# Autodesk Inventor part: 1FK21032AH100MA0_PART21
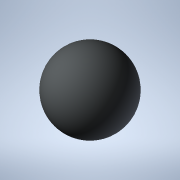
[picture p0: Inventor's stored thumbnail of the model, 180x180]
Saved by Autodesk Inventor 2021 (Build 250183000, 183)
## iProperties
Created: 2025-04
Part Number: 1FK21032AH100MA0_PART21
Material: Generic
Catalog Web Link: www.3dfindit.com
Description: -Servo synchronous motor
Document SubType Name: Modeling
Designer: psAdmin
Mass: 0.113097 g
Surface Area: 1.13097 cm^2
Volume: 0.113097 cm^3
Density: 1 g/cm^3
Appearance: PSOLRGB-212-217-219
Category: PARTsolutions
Title: 1FK21032AH100MA0_PART21
Author: Cadenas PARTsolutions
Comments: Servo synchronous motor
Sending System: PARTsolutions
Preprocessor: ST-DEVELOPER v19.3
PSOL_IDENT_0: {$CADENAS_DATA/23d-libs/siemens_ag/_cat_/12/33/1fk21032ah100ma0.prj},216 {VTYP=3D},{NB=1FK21032AH100
PSOL_IDENT_1: MA0_PART21},{LINA=1FK21032AH100MA0_PART21},{NN=1FK21032AH100MA0_PART21},{NOPRJ=TRUE},{DATE=19.08.202
PSOL_IDENT_2: 5 14:00:27},{GEOMDATE=30.07.2025 02:02:58},{VERSION=},{LINEID=10},{WBVAR=},{WBNUMERIC=}  {NB=1FK2103
PSOL_IDENT_3: 2AH100MA0_PART21},{LINA=1FK21032AH100MA0_PART21},{KT=DUMMY},{PREVIEW=../../../_pool_/d3/78/p_d211_xx
PSOL_IDENT_4: _00934j.png},{DESCSHORT=SIMOTICS S-1FK2 HD, SINAMICS S210 3AC 400V-480V, 0.59 Nm, 4500 rpm},{DESCLON
PSOL_IDENT_5: G=SIMOTICS S-1FK2 HD servo motor M0=0.64 Nm; PN = 0.28 kW at nN=4500 rpm (380-480 V); PN = 0.167 kW
PSOL_IDENT_6: at nN=2500 rpm (200-240 V); with holding brake; degree of protection IP64; cylindrical shaft D14 x 3
PSOL_IDENT_7: 0 mm; absolute encoder 22-bit + 12-bit multiturn (encoder AM22DQC); with OCC interface; plug size M1
PSOL_IDENT_8: 7, rotatable; SIMOTICS S-1FK2 servomotorfor a wide range of uses in industrial environments. SIMOTIC
PSOL_IDENT_9: S S‑1FK2 servomotors are compact synchronous motors with a high dynamic performance that set themsel
PSOL_IDENT_10: ves apart as a result of their high power density, degree of protection and overload capability. The
PSOL_IDENT_11: motors are available in two variants: as High Dynamic variant (highest dynamic performance as a res
PSOL_IDENT_12: ult of the low intrinsic moment of inertia for applications demanding a high dynamic performance wit
PSOL_IDENT_13: h low moved masses) - and as Compact variant (precise and stable closed-loop control for medium up t
PSOL_IDENT_14: o large moved masses as a result of a medium intrinsic moment of inertia). SIMOTICSS‑1FK2 servomotor
PSOL_IDENT_15: s fully exploit their strengths in a system with the SINAMICSS210 frequency converter and simple con
PSOL_IDENT_16: nection using the one cable connection (OCC). Advantages include the short control and positioning t
PSOL_IDENT_17: imes, fast and precise correction of disturbing quantities as well as stable control with a high dyn
PSOL_IDENT_18: amic performance. The servo motors can be configured to address a wide range of requirements. For ex
PSOL_IDENT_19: ample with and without holding brake, IP64 or IP65 degree of protection, singleturn or multiturn abs
PSOL_IDENT_20: olute encoders - to name just a few. Further, the servomotors are available in different shaft heigh
PSOL_IDENT_21: ts extending from 20 to 100. A shaft sealing ring is available to achieve an IP65 degree of protecti
PSOL_IDENT_22: on and for subsequent mounting at the motor or as spare part. SIMOTICS - the optimum motor for each
PSOL_IDENT_23: and every motion control application.},{INTNO=195125315563},{SUPPLIERALTNO=1FK2103-2AH10-0MA0},{MANU
PSOL_IDENT_24: ID=1FK21032AH100MA0},{MANUNAME=Siemens},{MANUTYPEDESC=SYNCHRONOUS MOTOR 1FK2 HD 0,64 NM},{AAU732=SIM
PSOL_IDENT_25: OTICS},{AAO057=S-1FK2},{AAU734=SIMOTICS S-1FK2 HD servo motor M0=0.64 Nm; PN = 0.28 kW at nN=4500 rp
PSOL_IDENT_26: m (380-480 V); PN = 0.167 kW at nN=2500 rpm (200-240 V); with holding brake; degree of protection IP
PSOL_IDENT_27: 64; cylindrical shaft D14 x 30 mm; absolute encoder 22-bit + 12-bit multiturn (encoder AM22DQC); wit
PSOL_IDENT_28: h OCC interface; plug size M17, rotatable;},{AAW338=SYNCHRONOUS MOTOR 1FK2 HD 0,64 NM},{AAO742=SIMOT
PSOL_IDENT_29: ICS},{AAO663=4034106444723},{NOCUPEROU=1},{PRICEQUANTITY=1},{QUANTITYMIN=1},{QUANTITYINT=1},{CTN=850
PSOL_IDENT_30: 15100},{COO=RO},{AAO676=1FK2103-2AH10-0MA0},{AAO677=Siemens AG},{ORDERUNIT=C62},{CONTENTUNIT=C62}
NB: 1FK21032AH100MA0_PART21
NT: Servo synchronous motor
NBSYN: $MANUID._PART21
LINA: 1FK21032AH100MA0_PART21
CATALOG: SIEMENS
PREVIEW: ../../../_pool_/d3/78/p_d211_xx_00934j.png
DESCSHORT: SIMOTICS S-1FK2 HD, SINAMICS S210 3AC 400V-480V, 0.59 Nm, 4500 rpm
DESCLONG: SIMOTICS S-1FK2 HD servo motor M0=0.64 Nm; PN = 0.28 kW at nN=4500 rpm (380-480 V); PN = 0.167 kW at nN=2500 rpm (200-240 V); with holding brake; degree of prot
INTNO: 195125315563
SUPPLIERALTNO: 1FK2103-2AH10-0MA0
MANUID: 1FK21032AH100MA0
MANUNAME: Siemens
MANUTYPEDESC: SYNCHRONOUS MOTOR 1FK2 HD 0,64 NM
AAU732: SIMOTICS
AAO057: S-1FK2
AAU734: SIMOTICS S-1FK2 HD servo motor M0=0.64 Nm; PN = 0.28 kW at nN=4500 rpm (380-480 V); PN = 0.167 kW at nN=2500 rpm (200-240 V); with holding brake; degree of prot
AAW338: SYNCHRONOUS MOTOR 1FK2 HD 0,64 NM
AAO742: SIMOTICS
AAO663: 4034106444723.0
NOCUPEROU: 1
PRICEQUANTITY: 1
QUANTITYMIN: 1
QUANTITYINT: 1
CTN: 85015100
COO: RO
ARTICLENO: 1FK21032AH100MA0_PART21
BOMINFO: 1FK21032AH100MA0_PART21
CREATOR: CADENAS GmbH
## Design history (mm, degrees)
feature "2025_04_17_15_06_16_0705"
body "Solid1"
